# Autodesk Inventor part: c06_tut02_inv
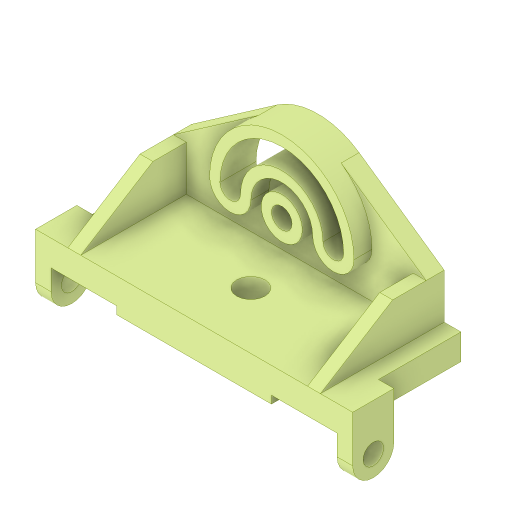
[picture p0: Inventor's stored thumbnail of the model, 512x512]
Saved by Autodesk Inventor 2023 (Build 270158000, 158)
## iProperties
Created: 2015-03
Part Number: c06_tut02_inv
Material: Generic
Document SubType Name: Modeling
Designer: Sandeep
Density: 1 g/cm^3
Appearance: Zinc Chromate 2
Author: Sandeep
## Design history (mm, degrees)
sketch "Sketch1"
  geometry: L1 (0, 0)-(-51, 0); L2 (-51, 0)-(-51, -6); L3 (-51, -6)-(-171, -6); L4 (-171, -6)-(-171, 0); L5 (-171, 0)-(-222, 0); L6 (-222, 0)-(-222, 20); L7 (-222, 20)-(0, 20); L8 (0, 20)-(0, 0)
  constraints: 16 end point, 6 perpendicular, 2 point on line, 1 horizontal
  dimensions: "d0" = 20 distance of L5.end L6.end; "d1" = 26 distance between parallel lines of L3 L7; "d2" = 120 distance of L4.end L1.end; "d3" = 51 distance between parallel lines of L2 L8; "d4" = 51 distance from line of L4.end L6
extrude "Extrusion1" new body sketch "Sketch1" distance "d5" = 96; taper "d6" = 0 deg
sketch "Sketch2"
  geometry: L1 (209, -20)-(209, -55); L2 (209, -55)-(143, -100.957); L3 (79, -100.957)-(13, -55); L4 (13, -55)-(13, -20); L5 (222, -20)-(0, -20) reference; L6 (13, -20)-(209, -20); L7 (222, -20)-(222, 0) reference; L8 (209, -55)-(-58.567, -55); A1 r 56 centre (111, -55) between (79, -100.957) and (143, -100.957); 1 further point
  constraints: 12 end point, 2 parallel, 2 point on circle, 2 point on line, 2 tangent, 1 centre point, 1 collinear, 1 horizontal, 1 vertical
  dimensions: "d7" = 13 distance from line of point (0, 0) L4; "d8" = 13 distance between parallel lines of L1 L7; "d10" = 56 radius of A1; "d11" = 98 distance from line of L1 A1.centre; "d13" = 35 distance of L1.start L1.end
extrude "Extrusion2" join sketch "Sketch2" distance "d14" = 14; taper "d15" = 0 deg
sketch "Sketch4"
  geometry: L1 (111, 55)-(-9.927, 55); C1 r 16 at (111, 55); A1 r 40 centre (111, 55) between (151, 55) and (71, 55); A2 r 56 centre (111, 55) between (167, 55) and (55, 55); A3 r 24 centre (111, 55) between (135, 55) and (87, 55); A4 r 16 centre (151, 55) between (135, 55) and (167, 55); A5 r 16 centre (71, 55) between (55, 55) and (87, 55); A6 r 56 centre (111, 55) between (143, 100.957) and (79, 100.957) reference
  constraints: 10 point on circle, 6 centre point, 4 tangent, 2 end point, 2 point on line, 1 coincident, 1 concentric, 1 horizontal
  dimensions: "d20" = 56 radius of A2; "d21" = 24 radius of A3; "d22" = 32 diameter of C1
extrude "Extrusion3" join sketch "Sketch4" distance "d23" = 14; taper "d24" = 0 deg
sketch "Sketch7"
  geometry: C1 r 8 at (111, 55); A1 r 16 centre (151, 55) between (135, 55) and (167, 55) reference; A2 r 16 centre (71, 55) between (55, 55) and (87, 55) reference; A3 r 40 centre (111, 55) between (151, 55) and (71, 55); A4 r 48 centre (111, 55) between (159, 55) and (63, 55); A5 r 32 centre (111, 55) between (143, 55) and (79, 55); A6 r 8 centre (151, 55) between (143, 55) and (159, 55); A7 r 8 centre (71, 55) between (63, 55) and (79, 55); A8 r 56 centre (111, 55) between (167, 55) and (55, 55) reference; 1 further point
  constraints: 10 point on circle, 6 centre point, 4 tangent, 1 coincident, 1 concentric
  dimensions: "d26" = 8 radius of A6; "d27" = 16 diameter of C1
extrude "Extrusion4" cut sketch "Sketch7" extent not by distance; stored distance "d28" = 14; taper "d29" = 0 deg
workplane "Work Plane1"
sketch "Sketch12"
  geometry: L1 (35, -96)-(35, 0) reference; L2 (35, -13.954)-(35, -96); L3 (35, -96)-(0, -40); L4 (0, -40)-(0, -14); L5 (0, 0)-(-45.957, 0) reference; 1 further point
  constraints: 6 end point, 1 collinear, 1 parallel, 1 point on line
  dimensions: "d34" = 35 distance between parallel lines of L1 L4; "d35" = 40 distance from line of L5 L3.end
feature "Rib1" sketch "Sketch12" dims "d36" = 1, "d37" = 10, "d38" = 0, "d39" = 0, "d40" = 1, "d41" = 1
sketch "Sketch14"
  geometry: L1 (0, 0)-(0, 32); L2 (0, 32)-(36, 32); L3 (36, 0)-(0, 0); L4 (0, 96)-(0, 0) reference; C1 r 8 at (36, 16); A1 r 16 centre (36, 16) between (36, 0) and (36, 32); 1 further point
  constraints: 6 end point, 2 centre point, 2 point on circle, 2 tangent, 1 coincident, 1 horizontal, 1 perpendicular, 1 point on line
  dimensions: "d42" = 36 distance from line of L1 A1.centre; "d43" = 16 radius of A1; "d44" = 16 diameter of C1
extrude "Extrusion5" join sketch "Sketch14" distance "d45" = 12; taper "d46" = 0 deg
workplane "Work Plane2"
mirror "Mirror1"
hole "Hole1" diameter "d50" = 22; stored, may be unused: countersink angle "d54" = 90 deg, drill point angle "d56" = 118 deg; dims "d48" = 88, "d49" = 38, "d51" = 6, "d52" = 4, "d53" = 2, "d55" = 8
body "Solid1"
other parameters: "d32" = 0, "d47" = -111
